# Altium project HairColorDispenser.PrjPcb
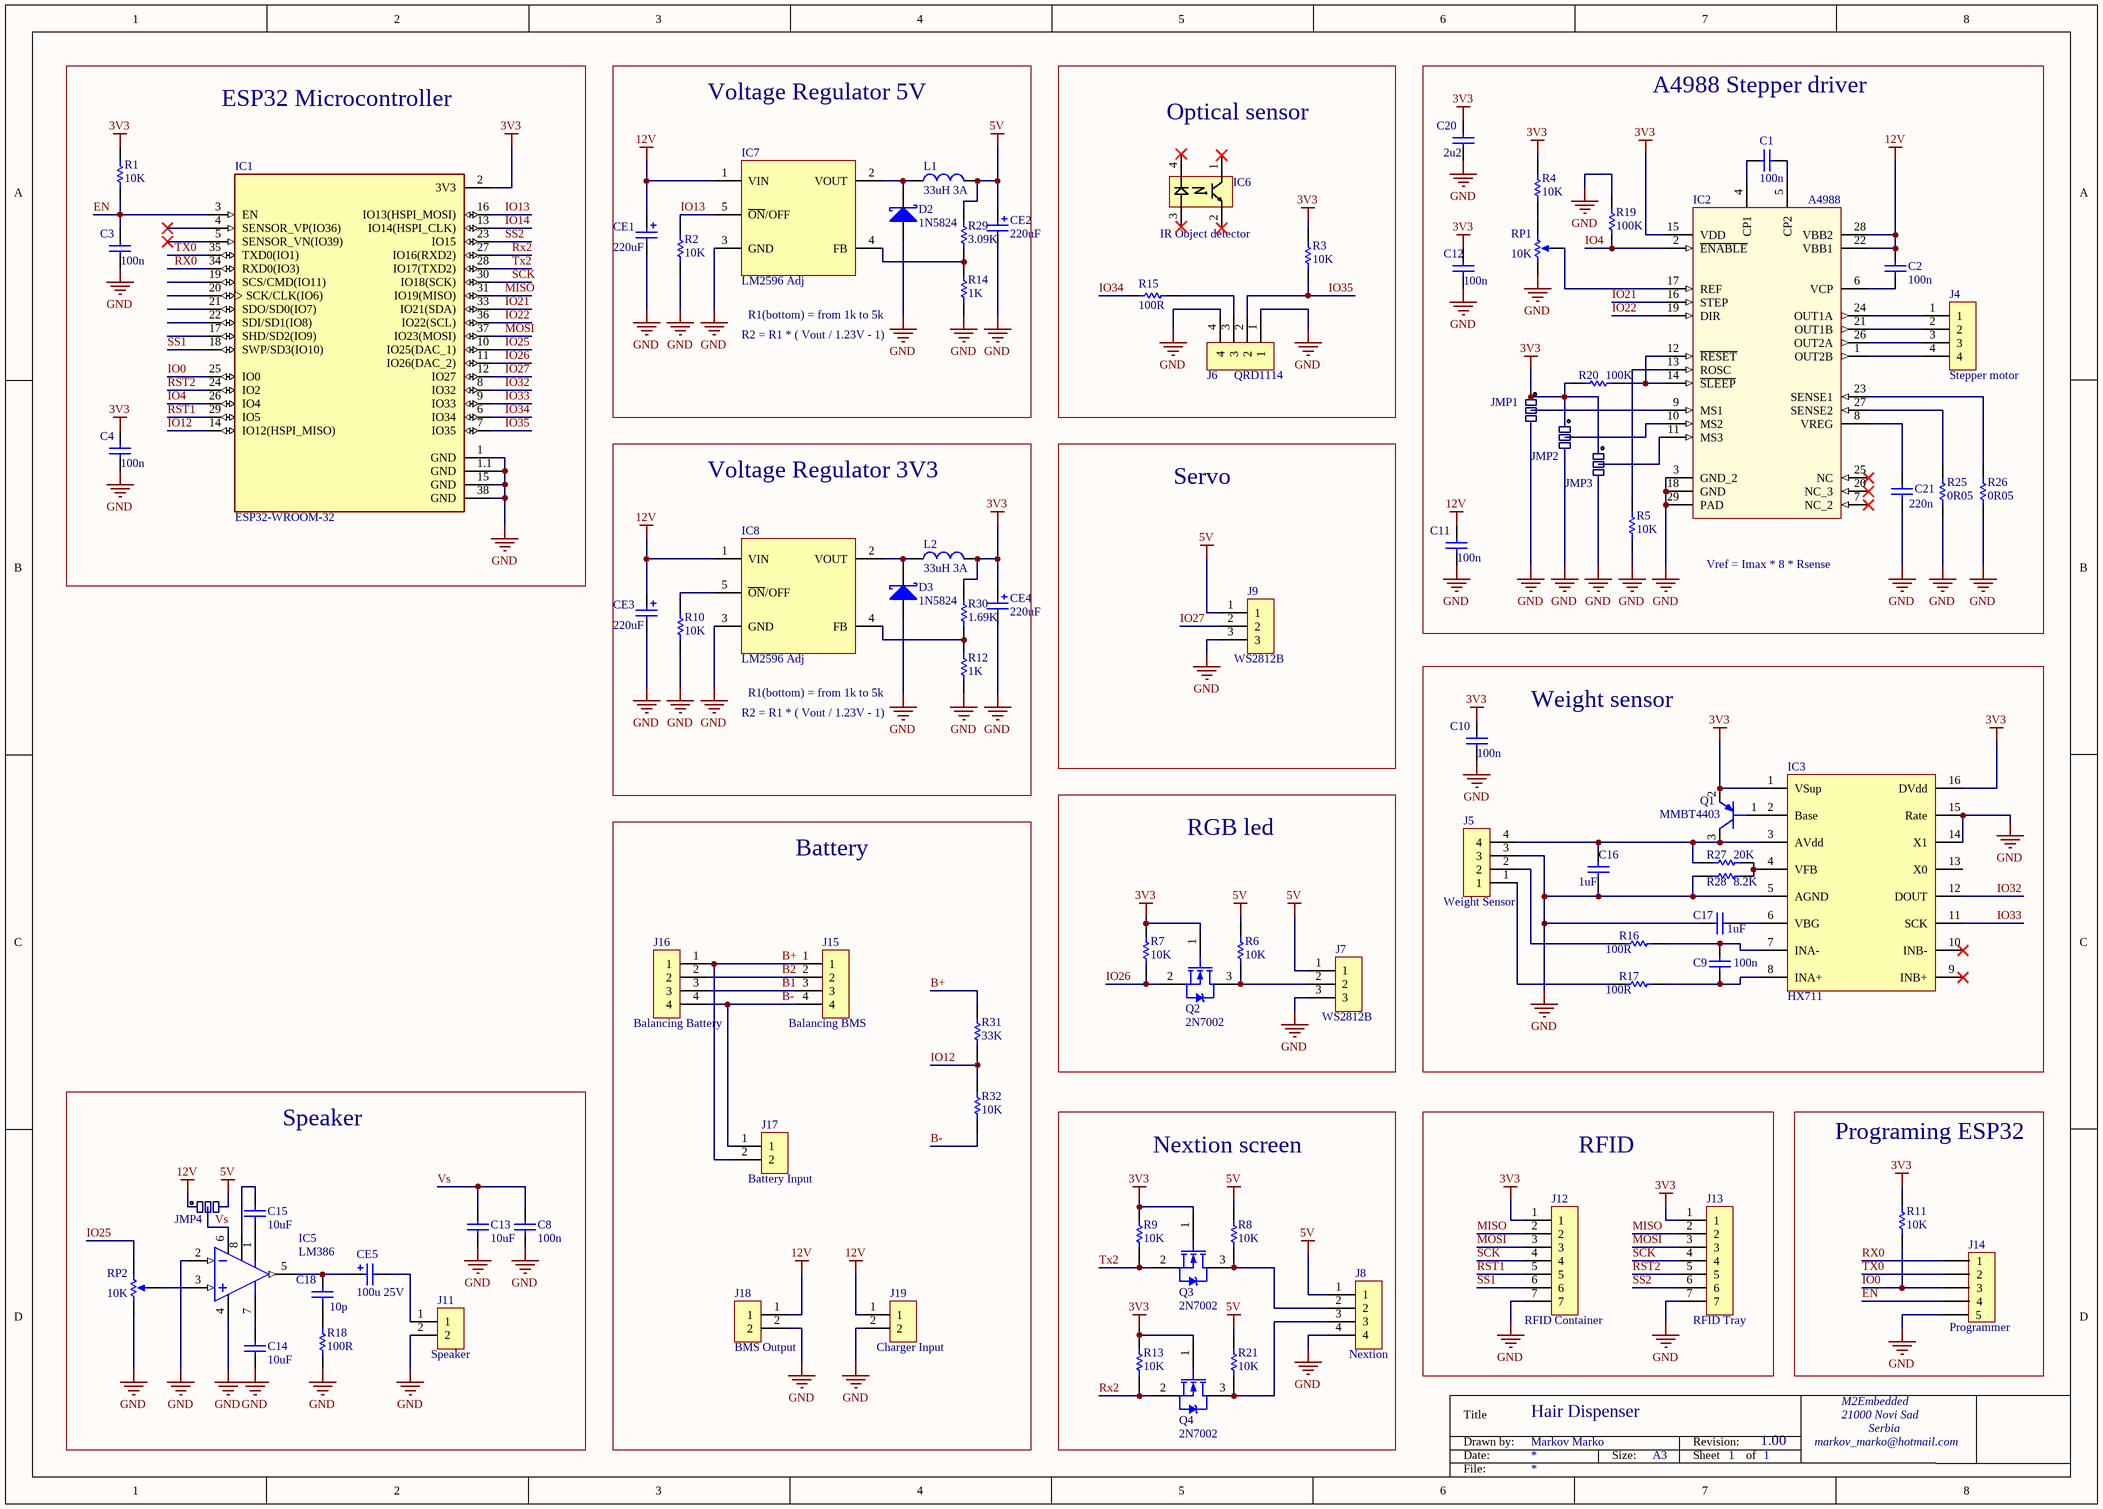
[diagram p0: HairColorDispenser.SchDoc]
1 sheet, 87 parts. Net scope: global (net labels, ports and power ports of the same name join across sheets).
Board file: HairColorDispenser.PcbDoc

## Sheet HairColorDispenser.SchDoc: Hair Dispenser
size A3; DrawnBy: Markov Marko; Engineer: Markov Marko; Organization: M2Embedded; Address1: 21000 Novi Sad; Address2: Serbia; Address3: markov_marko@hotmail.com; Revision: 1.00; SheetNumber: 1; SheetTotal: 1; Design Engeneer:: Markov Marko

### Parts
C1  100n  [CAPC3216X18N]
C2  100n  [CAPC3216X18N]
C3  100n  [CAPC3216X18N]
C4  100n  [CAPC3216X18N]
C8  100n  [CAPC3216X18N]
C9  100n  [CAPC3216X18N]
C10  100n  [CAPC3216X18N]
C11  100n  [CAPC3216X18N]
C12  100n  [CAPC3216X18N]
C13  10uF  [CAPC3216X18N]
C14  10uF  [CAPC3216X18N]
C15  10uF  [CAPC3216X18N]
C16  1uF  [CAPC3216X18N]
C17  1uF  [CAPC3216X18N]
C18  10p  [CAPC3216X18N]
C20  2u2  [CAPC3216X18N]
C21  220n  [CAPC3216X18N]
CE1  220uF  [220uF 35V]
CE2  220uF  [220uF 35V]
CE3  220uF  [220uF 35V]
CE4  220uF  [220uF 35V]
CE5  100u 25V  [CAPAE800X550N]
D2  1N5824  [SOD128]
D3  1N5824  [SOD128]
IC1  ESP32-WROOM-32  [MODULE_ESP-WROOM-32]
IC2  A4988  [28-QFN (5x5)]
IC3  HX711  [SOP16]
IC5  LM386  [SOIC-8]
IC6  IR Object detector  [QRD1114]  (no BOM)
IC7  LM2596 Adj  [TO263-5]
IC8  LM2596 Adj  [TO263-5]
J4  Stepper motor  [B4B-HX-A]
J5  Weight Sensor  [B4B-HX-A]
J6  QRD1114  [B4B-HX-A]
J7  WS2812B  [B3B-HX-A]
J8  Nextion  [B4B-HX-A]
J9  WS2812B  [B3B-HX-A]
J11  Speaker  [B2B-XH-A]
J12  RFID Container  [B7B-HX-A]
J13  RFID Tray  [B7B-HX-A]
J14  Programmer  [HEADER1X5]
J15  Balancing BMS  [B4B-HX-A]
J16  Balancing Battery  [B4B-HX-A]
J17  Battery Input  [B2B-XH-A]
J18  BMS Output  [B2B-XH-A]
J19  Charger Input  [B2B-XH-A]
JMP1  0R  [JMP_SOLDER_3]  (value not drawn)
JMP2  0R  [JMP_SOLDER_3]  (value not drawn)
JMP3  0R  [JMP_SOLDER_3]  (value not drawn)
JMP4  0R  [JMP_SOLDER_3]  (value not drawn)
L1  33uH 3A  [33uH 3A]
L2  33uH 3A  [33uH 3A]
Q1  MMBT4403  [SOT95P230X126-3N]
Q2  2N7002  [SOT95P230X126-3N]
Q3  2N7002  [SOT95P230X126-3N]
Q4  2N7002  [SOT95P230X126-3N]
R1  10K  [SMD 1206]
R2  10K  [SMD 1206]
R3  10K  [SMD 1206]
R4  10K  [SMD 1206]
R5  10K  [SMD 1206]
R6  10K  [SMD 1206]
R7  10K  [SMD 1206]
R8  10K  [SMD 1206]
R9  10K  [SMD 1206]
R10  10K  [SMD 1206]
R11  10K  [SMD 1206]
R12  1K  [SMD 1206]
R13  10K  [SMD 1206]
R14  1K  [SMD 1206]
R15  100R  [SMD 1206]
R16  100R  [SMD 1206]
R17  100R  [SMD 1206]
R18  100R  [SMD 1206]
R19  100K  [SMD 1206]
R20  100K  [SMD 1206]
R21  10K  [SMD 1206]
R25  0R05  [SMD 1206]
R26  0R05  [SMD 1206]
R27  20K  [SMD 1206]
R28  8.2K  [SMD 1206]
R29  3.09K  [SMD 1206]
R30  1.69K  [SMD 1206]
R31  33K  [SMD 1206]
R32  10K  [SMD 1206]
RP1  10K  [SMD POT]
RP2  10K  [SMD POT]

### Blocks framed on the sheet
ESP32 Microcontroller: C3 C4 IC1 R1
Voltage Regulator 5V: CE1 CE2 D2 IC7 L1 R2 R14 R29
Optical sensor: IC6 J6 R3 R15
A4988 Stepper driver: C1 C2 C11 C12 C20 C21 IC2 J4 JMP1-JMP3 R4 R5 R19 R20 R25 R26 RP1
Voltage Regulator 3V3: CE3 CE4 D3 IC8 L2 R10 R12 R30
Servo: J9
Weight sensor: C9 C10 C16 C17 IC3 J5 Q1 R16 R17 R27 R28
Battery: J15-J19 R31 R32
RGB led: J7 Q2 R6 R7
Speaker: C8 C13-C15 C18 CE5 IC5 J11 JMP4 R18 RP2
Nextion screen: J8 Q3 Q4 R8 R9 R13 R21
RFID: J12 J13
Programing ESP32: J14 R11

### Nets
3V3: C4.2 C10.2 C12.2 C20.2 CE4.1 IC1.2(3V3) IC2.15(VDD) IC3.1(VSup) IC3.16(DVdd) J12.1 J13.1 JMP1.1 JMP2.1 JMP3.1 L2.2 Q1.2(E) Q2.1(G) Q3.1(G) Q4.1(G) R1.2 R3.2 R4.2 R7.2 R9.2 R11.1 R13.2 R20.2 R30.1
5V: CE2.1 J7.1 J8.1 J9.1 JMP4.3 L1.2 R6.1 R8.1 R21.1 R29.1
12V: C2.2 C11.2 CE1.1 CE3.1 IC2.22(VBB1) IC2.28(VBB2) IC7.1(VIN) IC8.1(VIN) J18.1 J19.1 JMP4.1
GND: C3.1 C4.1 C8.1 C10.1 C11.1 C12.1 C13.1 C14.1 C16.1 C17.1 C20.1 C21.1 CE1.2 CE2.2 CE3.2 CE4.2 D2.2(A) D3.2(A) IC1.1(GND) IC1.1.1(GND) IC1.15(GND) IC1.38(GND) IC2.3(GND_2) IC2.18(GND) IC2.29(PAD) IC3.5(AGND) IC3.14(X1) IC3.15(Rate) IC5.2(IN-) IC5.4(V-) IC7.3(GND) IC8.3(GND) J5.3 J6.1 J6.4 J7.3 J8.4 J9.3 J11.2 J12.7 J13.7 J14.5 J18.2 J19.2 JMP1.3 JMP2.3 JMP3.3 R2.1 R5.1 R10.1 R12.1 R14.1 R18.2 R19.2 R25.2 R26.2 R28.1 RP1.1(CCW) RP2.1(CCW)
B1: J15.3 J16.3
B2: J15.2 J16.2
B+: J15.1 J16.1 J17.2 R31.2
B-: J15.4 J16.4 J17.1 R32.1
EN: C3.2 IC1.3(EN) J14.4 R1.1
IO0: IC1.25(IO0) J14.3 R11.2
IO4: IC1.26(IO4) IC2.2(~{ENABLE}) R19.1
IO12: IC1.14(IO12(HSPI_MISO)) R31.1 R32.2
IO13: IC1.16(IO13(HSPI_MOSI)) IC7.5(~{ON}/OFF) R2.2
IO14: IC1.13(IO14(HSPI_CLK))
IO21: IC1.33(IO21(SDA)) IC2.16(STEP)
IO22: IC1.36(IO22(SCL)) IC2.19(DIR)
IO25: IC1.10(IO25(DAC_1)) RP2.3(CW)
IO26: IC1.11(IO26(DAC_2)) Q2.2(S) R7.1
IO27: IC1.12(IO27) J9.2
IO32: IC1.8(IO32) IC3.12(DOUT)
IO33: IC1.9(IO33) IC3.11(SCK)
IO34: IC1.6(IO34) R15.1
IO35: IC1.7(IO35) J6.2 R3.1
MISO: IC1.31(IO19(MISO)) J12.2 J13.2
MOSI: IC1.37(IO23(MOSI)) J12.3 J13.3
RST1: IC1.29(IO5) J12.5
RST2: IC1.24(IO2) J13.5
RX0: IC1.34(RXD0(IO3)) J14.1
Rx2: IC1.27(IO16(RXD2)) Q4.2(S) R13.1
SCK: IC1.30(IO18(SCK)) J12.4 J13.4
SS1: IC1.18(SWP/SD3(IO10)) J12.6
SS2: IC1.23(IO15) J13.6
TX0: IC1.35(TXD0(IO1)) J14.2
Tx2: IC1.28(IO17(TXD2)) Q3.2(S) R9.1
Vs: C8.2 C13.2 IC5.6(Vcc) JMP4.2
NetC1_1: C1.1 IC2.4(CP1)
NetC1_2: C1.2 IC2.5(CP2)
NetC2_1: C2.1 IC2.6(VCP)
NetC9_1: C9.1 IC3.8(INA+) R17.2
NetC9_2: C9.2 IC3.7(INA-) R16.2
NetC14_2: C14.2 IC5.7(Bypass)
NetC15_1: C15.1 IC5.1(REF_1)
NetC15_2: C15.2 IC5.8(GAIN)
NetC16_2: C16.2 IC3.3(AVdd) J5.4 Q1.3(C) R27.1
NetC17_2: C17.2 IC3.6(VBG)
NetC18_1: C18.1 CE5.1 IC5.5(OUT)
NetC18_2: C18.2 R18.1
NetC21_2: C21.2 IC2.8(VREG)
NetCE5_2: CE5.2 J11.1
NetD2_1: D2.1(K) IC7.2(VOUT) L1.1
NetD3_1: D3.1(K) IC8.2(VOUT) L2.1
NetIC2_1: IC2.1(OUT2B) J4.4
NetIC2_9: IC2.9(MS1) JMP1.2
NetIC2_10: IC2.10(MS2) JMP2.2
NetIC2_11: IC2.11(MS3) JMP3.2
NetIC2_12: IC2.12(~{RESET}) IC2.14(~{SLEEP}) R20.1
NetIC2_13: IC2.13(ROSC) R5.2
NetIC2_17: IC2.17(REF) RP1.2(WIPER)
NetIC2_21: IC2.21(OUT1B) J4.2
NetIC2_23: IC2.23(SENSE1) R26.1
NetIC2_24: IC2.24(OUT1A) J4.1
NetIC2_26: IC2.26(OUT2A) J4.3
NetIC2_27: IC2.27(SENSE2) R25.1
NetIC3_2: IC3.2(Base) Q1.1(B)
NetIC3_4: IC3.4(VFB) R27.2 R28.2
NetIC5_3: IC5.3(IN+) RP2.2(WIPER)
NetIC7_4: IC7.4(FB) R14.2 R29.2
NetIC8_4: IC8.4(FB) R12.2 R30.2
NetIC8_5: IC8.5(~{ON}/OFF) R10.2
NetJ5_1: J5.1 R17.1
NetJ5_2: J5.2 R16.1
NetJ6_3: J6.3 R15.2
NetJ7_2: J7.2 Q2.3(D) R6.2
NetJ8_2: J8.2 Q3.3(D) R8.2
NetJ8_3: J8.3 Q4.3(D) R21.2
NetR4_1: R4.1 RP1.3(CW)

Not connected (* = marked no-connect by the designer): IC1 4(SENSOR_VP(IO36))* 5(SENSOR_VN(IO39))* 17(SHD/SD2(IO9)) 19(SCS/CMD(IO11)) 20(SCK/CLK(IO6)) 21(SDO/SD0(IO7)) 22(SDI/SD1(IO8)); IC2 7(NC_2)* 20(NC_3)* 25(NC)*; IC3 9(INB+)* 10(INB-)* 13(X0); IC6 1(C)* 2(E)* 3(A)* 4(K)*

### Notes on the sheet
- R1(bottom) = from 1k to 5k
- R2 = R1 * ( Vout / 1.23V - 1)
- Vref = Imax * 8 * Rsense

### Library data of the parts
C1 C2 = 100n 25V NP0: CAP CER 0.1UF 25V NP0 1206; Manufacturer: Murata Electronics North America; Manufacturer Code: GRM31C5C1E104JA01L; Ordering Code: 490-1767-1-ND
C3 C4 C8-C12 = 100n 50V X7R: CAP CER 0.1UF 50V X7R 1206; Manufacturer: KEMET; Manufacturer Code: C1206C104K5RAC7800; Ordering Code: 399-C1206C104K5RAC7800CT-ND
C13-C15 = 10uF 25V X7R: CAP CER 10UF 25V X5R 1206; Manufacturer: KEMET; Manufacturer Code: C1206C106M3PACTU; Ordering Code: 399-8153-1-ND
C16 C17 = 1uF 25V X7R: CAP CER 1UF 25V X7R 1206; Manufacturer: KEMET; Manufacturer Code: C1206C105M3RACTU; Ordering Code: 399-8148-1-ND
C18 = 10p 50V X7R: CAP CER 10pF 50V NP0 1206; Manufacturer: KEMET; Manufacturer Code: C1206C100J5GACAUTO; Ordering Code: 399-C1206C100J5GACAUTOCT-ND
C20 = 2u2 50V X7R: CAP CER 2.2UF 50V X7R 1206; Manufacturer: KEMET; Manufacturer Code: C1206C225K5RACAUTO; Ordering Code: 399-7019-1-ND
C21 = 220n 50V X7R: CAP CER 0.22UF 50V X7R 1206; Manufacturer: KEMET; Manufacturer Code: C1206C224K5RACTU; Ordering Code: 399-1251-1-ND
CE1-CE4 = 220u 35V: CAP ALUM 220UF 20% 35V SMD; Manufacturer Code: UWT1V221MNL1GS; Manufacturer: Nichicon; Ordering code: 493-2205-1-ND
CE5 = 100u 25V h=5.4mm: CAPAE800X700 CASE E PANASONIC_EEEFK1E101P; Manufacturer Code: UWX1E101MCL1GB; Manufacturer: Nichicon; Ordering code: 493-2113-1-ND
D2 D3 = 1N5824: DIODE SCHOTTKY 30V 5A MFLAT; Manufacturer: Toshiba Semiconductor and Storage; Manufacturer code: CMS04(TE12L,Q,M); Ordering Code: 1N5819HW-FDICT-ND
IC1 = ESP32-WROOM-32: Bluetooth, WiFi Transceiver Module 2.4GHz ~ 2.5GHz Surface Mount; Manufacturer: Espressif Systems; Ordering Code: 1904-1010-1-ND
IC2 = A4988: IC MTR DRVR BIPOLAR 3-5.5V 28QFN; Manufacturer Code: A4988SETTR-T; Manufacturer: Allegro MicroSystems; Ordering Code: 620-1343-1-ND
IC3 = HX711: LOAD CELL AMP HX711
IC5 = LM386: IC AMP AUDIO PWR .325W AB 8SOIC; Manufacturer: Texas Instruments; Manufacturer Code: LM386MX-1/NOPB; Ordering Code: LM386MX-1/NOPBCT-ND
IC6 = QRD1114: SENSR OPTO TRANS 1.27MM REFL PCB; Manufacturer: ON Semiconductor; Distibutor: Digi-Key; Ordering code: QRD1114-ND
IC7 IC8 = LM2596 Adj: IC REG MULT CONFG ADJ 3A D2PAK-5; Manufacturer Code: LM2596DSADJG; Manufacturer: ON Semiconductor; Ordering Code: LM2596DSADJGOS-ND
J4-J6 J8 J15 J16 = JST 4-Pin 2.5mm B4B-XH-A: CONN HEADER XH TOP 2POS 2.5MM; Manufacturer: JST Sales America Inc.; Manufacturer Code: B4B-XH-A(LF)(SN); Order Code: 455-2249-ND
J7 J9 = JST 3-Pin 2.5mm B3B-XH-A: CONN HEADER XH TOP 2POS 2.5MM; Manufacturer: JST Sales America Inc.; Manufacturer Code: B3B-XH-A(LF)(SN); Order Code: 455-2248-ND
J11 J17-J19 = JST 2-Pin 2.5mm B2B-XH-A: CONN HEADER XH TOP 2POS 2.5MM; Manufacturer: JST Sales America Inc.; Manufacturer Code: B2B-XH-A(LF)(SN); Order Code: 455-2247-ND
J12 J13 = JST 7-Pin 2.5mm B7B-XH-A: CONN HEADER VERT 7POS 2.5MM; Manufacturer: JST Sales America Inc.; Manufacturer Code: B7B-XH-A(LF)(SN); Order Code: 455-2252-ND
J14 = Header 1x5: CONN HEADER VERT 5POS 2.54MM; Manufacturer: Harwin Inc.; Manufacturer Code: M20-9990546; Ordering Code: 952-2268-ND
JMP1-JMP4 = JMP-3 0R0 0603: Solder Jumper 3x0603
L1 L2 = IND 33u 3A: FIXED IND 33UH 3A 60 MOHM SMD; Manufacturer: Bourns Inc.; Manufacturer Code: SRR1260-330M; Ordering Code: SRR1260-330MTR-ND
Q1 = MMBT4403: PNP 40V 600mA 200MHz 300mW SOT-23-3; Manufacturer: ON Semiconductor; Manufacturer Code: MMBT4403LT1G; Ordering Code: MMBT4403LT1GOSCT-ND
Q2-Q4 = 2N7002: MOSFET N-CH 60V 115mA SOT-23; Manufacturer: ON Semiconductor; Ordering Code: 2N7002NCT-ND
R1-R11 R13 R21 R32 = 10K 1% 0.25W: RES SMD 10K OHM 1% 1/4W 1206; Manufacturer: Yageo; Manufacturer Code: RC1206FR-0710KL; Ordering Code: 311-10.0KFRCT-ND
R12 R14 = 1K 1% 0.25W: RES SMD 1K OHM 1% 1/4W 1206; Manufacturer: Yageo; Manufacturer Code: RC1206FR-071KL; Ordering Code: 311-1.00KFRCT-ND
R15-R18 = 100R 1% 0.25W: RES SMD 100 OHM 1% 1/4W 1206; Manufacturer: Yageo; Manufacturer Code: RC1206FR-07100RL; Ordering Code: 311-100FRCT-ND
R19 R20 = 100K 1% 0.25W: RES SMD 100K OHM 1% 1/4W 1206; Manufacturer: Yageo; Manufacturer Code: RC1206FR-07100KL; Ordering Code: 311-100KFRCT-ND
R25 R26 = 0R05 0.5% 0.5W: RES 50M OHM 0.5% 1/2W 1206; Manufacturer: Ohmite; Manufacturer Code: KDV12DR050ET; Order Code: 273-KDV12DR050ETCT-ND
R27 = 20K 1% 0.25W: RES SMD 20K OHM 1% 1/4W 1206; Manufacturer: Yageo; Manufacturer Code: RC1206FR-0720KL; Ordering Code: 311-20.0KFRCT-ND
R28 = 8K2 1% 0.25W: RES SMD 8.2K OHM 5% 1/4W 1206; Manufacturer: Yageo; Manufacturer Code: RC1206JR-078K2L; Ordering Code: 311-8.2KERCT-ND
R29 = 3.09K 1% 0.25W: RES SMD 3.09K OHM 1% 0.25W 1206; Manufacturer: Yageo; Manufacturer Code: RC1206FR-073K09L; Order Code: 311-3.09KFRCT-ND
R30 = 1.69K 1% 0.25W_1: RES SMD 1.69K OHM 1% 0.25W 1206; Manufacturer: Yageo; Manufacturer Code: RC1206FR-071K69L; Order Code: 311-1.69KFRCT-ND
R31 = 33K 1% 0.25W: RESISTOR, POWER, 1206, 1%, 33K; Manufacturer: Yageo; Manufacturer Code: RC1206FR-0733KL; Ordering Code: 311-33.0KFRCT-ND
RP1 RP2 = 10k POT SMD: TRIMMER 10K OHM 0.1W SMD; Manufacturer: Bourns Inc.; Manufacturer Code: TC33X-2-103E; Ordering Code: TC33X-103ECT-ND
